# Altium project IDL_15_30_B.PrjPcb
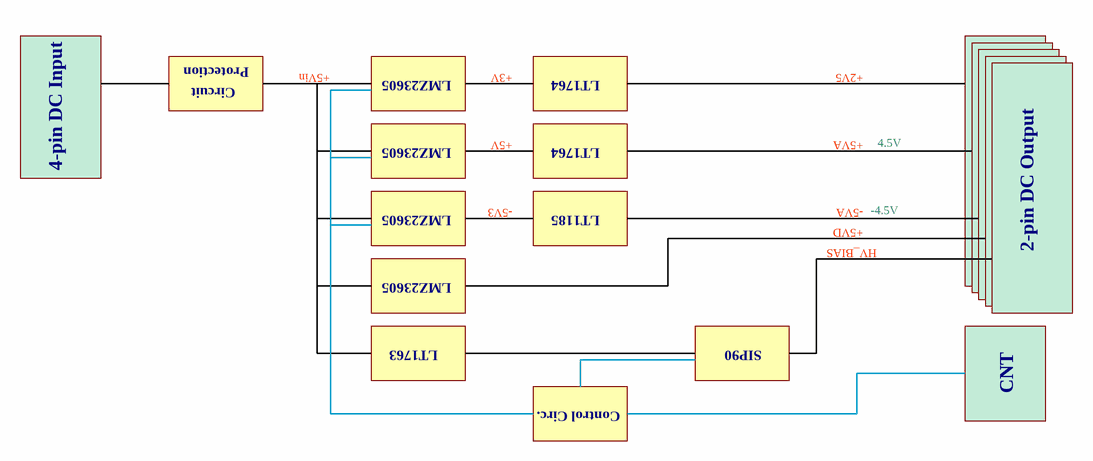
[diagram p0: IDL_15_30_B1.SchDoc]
Approved_By: Gary S. Varner; BoardName: CSciFi Power Supply; Designer: Peter Orel; Drawn_By: Peter Orel; IDLnum: IDL_15_30; ProjectName1: Compact SciFi Tracker; RevNum: B
3 sheets, 140 parts. Net scope: flat (ports and power ports of the same name join across sheets).
Board files: IDL_15_30_B.PcbDoc, IDL_15_30_B_pnl.PcbDoc
Sheets:
  IDL_15_30_B1.SchDoc
  IDL_15_30_B2.SchDoc
  PRJHdr_IDL_15_30_B.SchDoc

## Sheet IDL_15_30_B1.SchDoc: Functional Block Schematic
size 401 x 291 mm; DocumentNumber: 2; SheetNumber: 2; SheetTotal: 3

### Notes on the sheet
- Circuit
- Protection
- +5Vin
- LMZ23605
- +3V
- LT1764
- +2V5
- +5V
- +5VA
- 4.5V
- 4-pin DC Input
- -5V3
- LT1185
- -5VA
- +5VD
- -4.5V
- HV_BIAS
- 2-pin DC Output
- LT1763
- SIP90
- Control Circ.
- CNT

## Sheet IDL_15_30_B2.SchDoc: Power Supply Generation and Distribution
size 401 x 291 mm; DocumentNumber: 3; SheetNumber: 3; SheetTotal: 3
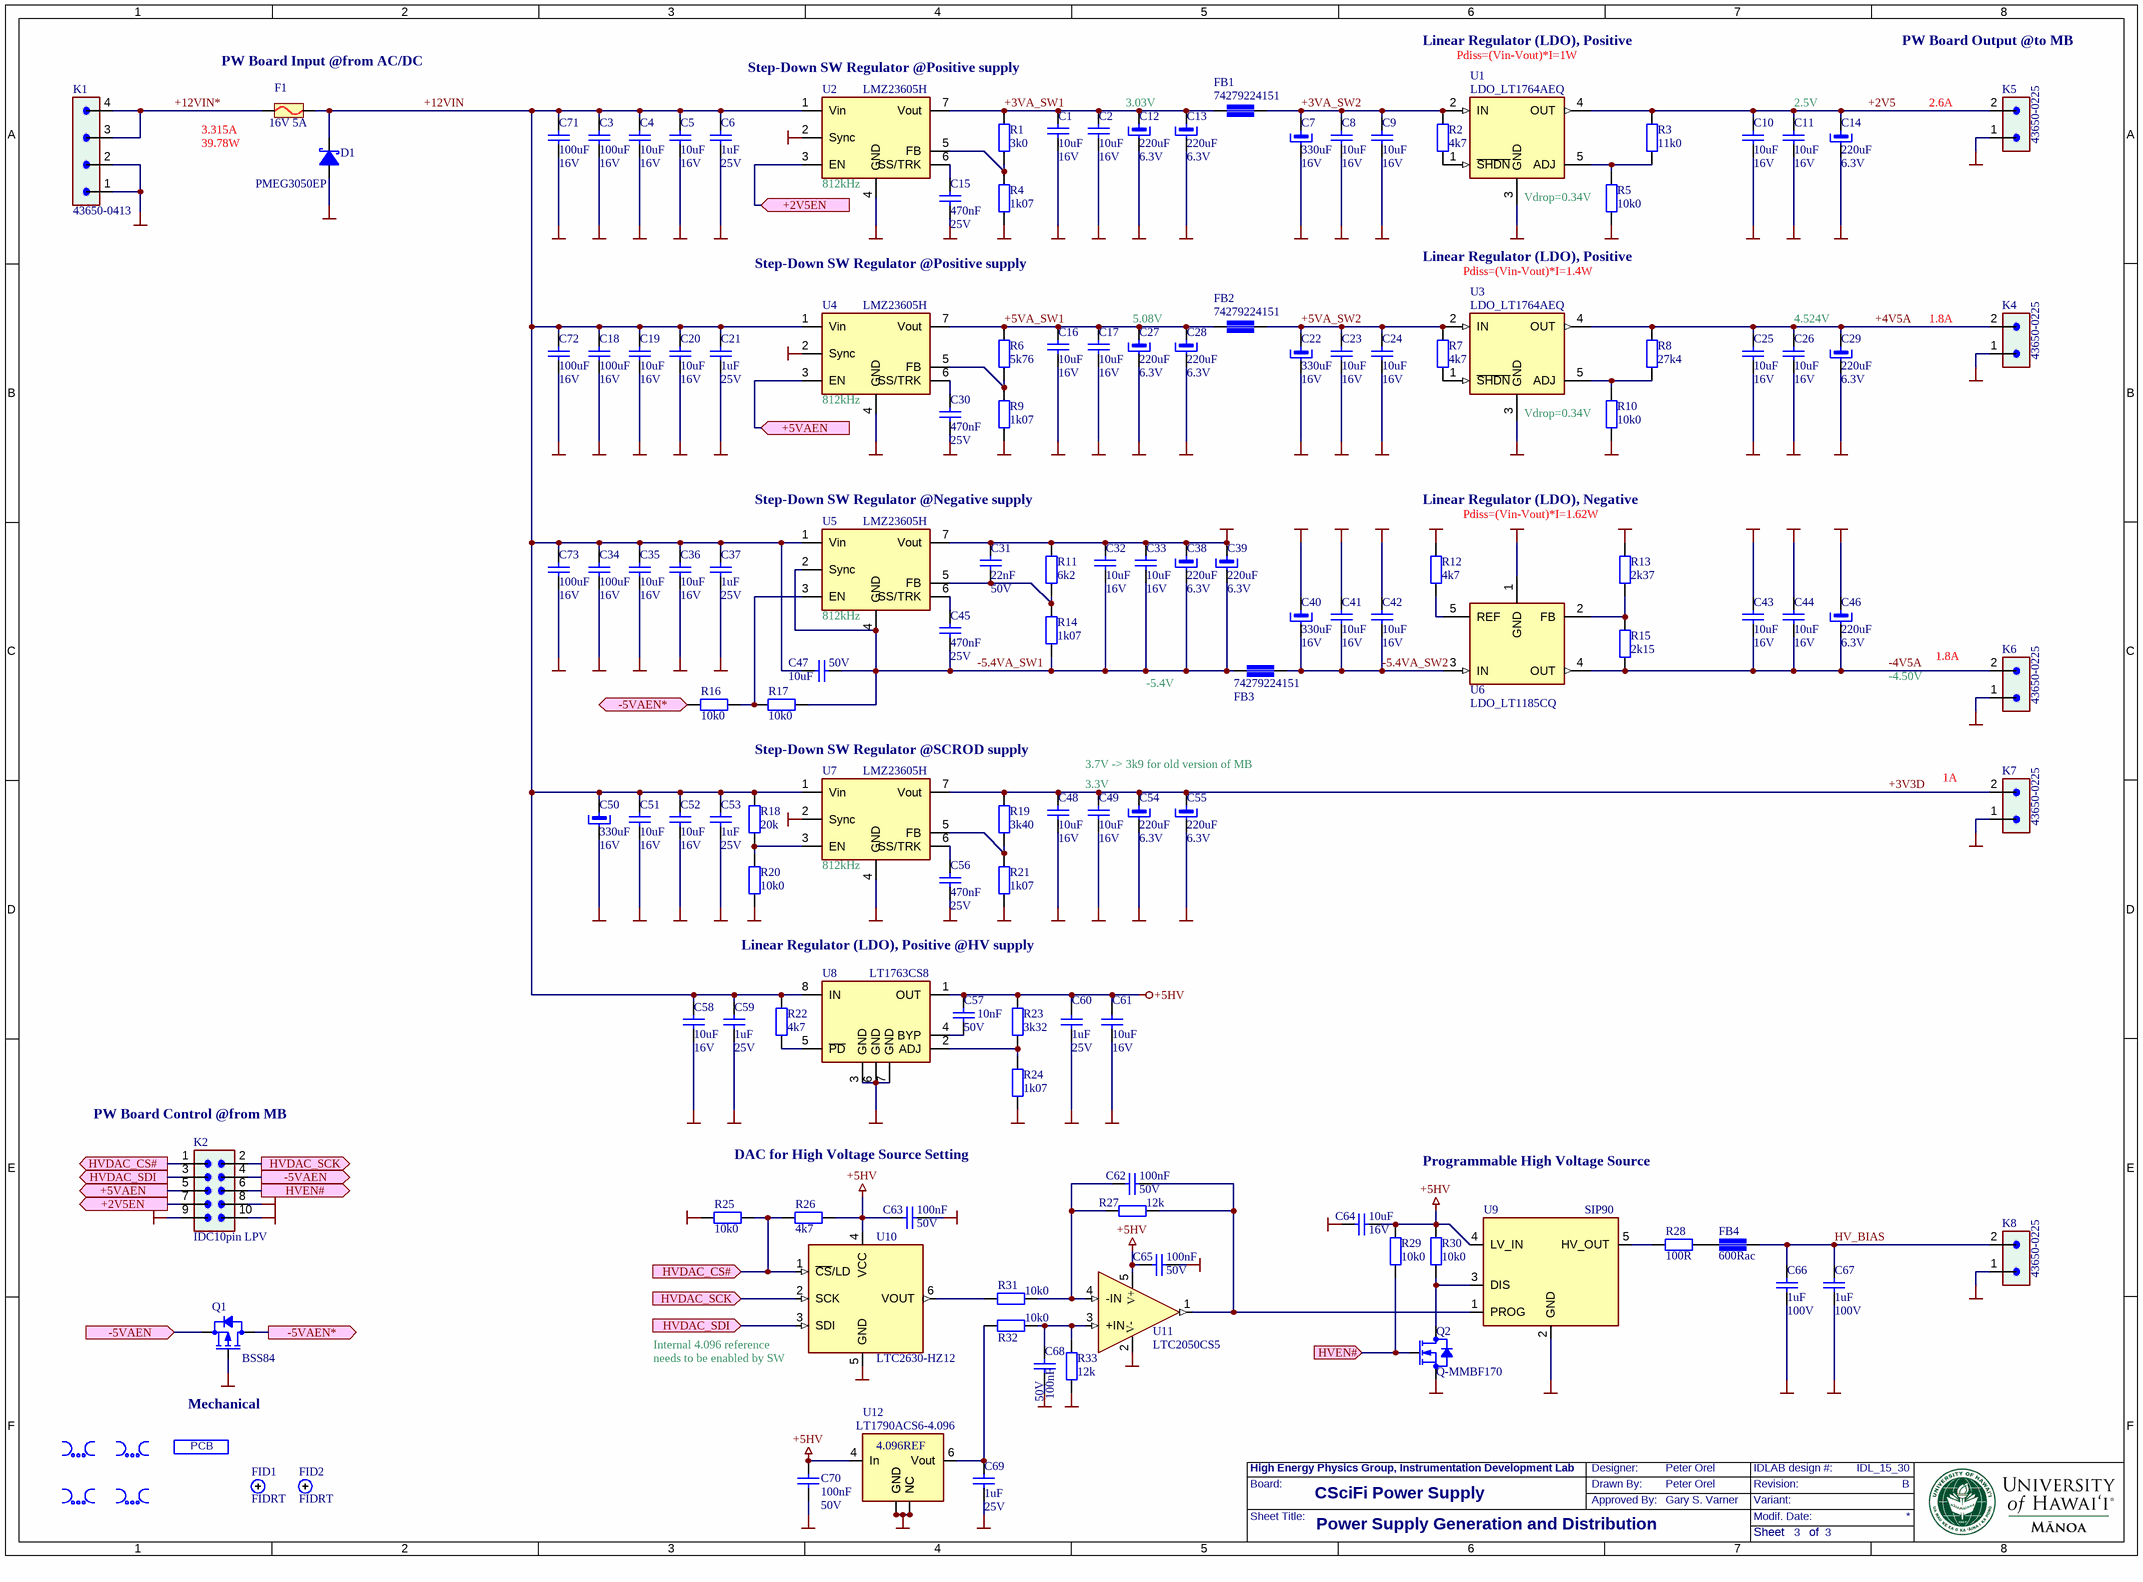
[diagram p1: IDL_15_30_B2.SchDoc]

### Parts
C1  10uF  Voltage rating: 16V  [CC1206N1R]
C2  10uF  Voltage rating: 16V  [CC1206N1R]
C3  100uF  Voltage rating: 16V  [CC1210N1R]
C4  10uF  Voltage rating: 16V  [CC1206N1R]
C5  10uF  Voltage rating: 16V  [CC1206N1R]
C6  1uF  Voltage rating: 25V  [CC0805N1R]
C7  330uF  Voltage rating: 16V  [CTC-D7343-43]
C8  10uF  Voltage rating: 16V  [CC1206N1R]
C9  10uF  Voltage rating: 16V  [CC1206N1R]
C10  10uF  Voltage rating: 16V  [CC1206N1R]
C11  10uF  Voltage rating: 16V  [CC1206N1R]
C12  220uF  Voltage rating: 6.3V  [CTC-D7343-43]
C13  220uF  Voltage rating: 6.3V  [CTC-D7343-43]
C14  220uF  Voltage rating: 6.3V  [CTC-D7343-43]
C15  470nF  Voltage rating: 25V  [CC0603RF1R]
C16  10uF  Voltage rating: 16V  [CC1206N1R]
C17  10uF  Voltage rating: 16V  [CC1206N1R]
C18  100uF  Voltage rating: 16V  [CC1210N1R]
C19  10uF  Voltage rating: 16V  [CC1206N1R]
C20  10uF  Voltage rating: 16V  [CC1206N1R]
C21  1uF  Voltage rating: 25V  [CC0805N1R]
C22  330uF  Voltage rating: 16V  [CTC-D7343-43]
C23  10uF  Voltage rating: 16V  [CC1206N1R]
C24  10uF  Voltage rating: 16V  [CC1206N1R]
C25  10uF  Voltage rating: 16V  [CC1206N1R]
C26  10uF  Voltage rating: 16V  [CC1206N1R]
C27  220uF  Voltage rating: 6.3V  [CTC-D7343-43]
C28  220uF  Voltage rating: 6.3V  [CTC-D7343-43]
C29  220uF  Voltage rating: 6.3V  [CTC-D7343-43]
C30  470nF  Voltage rating: 25V  [CC0603RF1R]
C31  22nF  Voltage rating: 50V  [CC0603RF1R]
C32  10uF  Voltage rating: 16V  [CC1206N1R]
C33  10uF  Voltage rating: 16V  [CC1206N1R]
C34  100uF  Voltage rating: 16V  [CC1210N1R]
C35  10uF  Voltage rating: 16V  [CC1206N1R]
C36  10uF  Voltage rating: 16V  [CC1206N1R]
C37  1uF  Voltage rating: 25V  [CC0805N1R]
C38  220uF  Voltage rating: 6.3V  [CTC-D7343-43]
C39  220uF  Voltage rating: 6.3V  [CTC-D7343-43]
C40  330uF  Voltage rating: 16V  [CTC-D7343-43]
C41  10uF  Voltage rating: 16V  [CC1206N1R]
C42  10uF  Voltage rating: 16V  [CC1206N1R]
C43  10uF  Voltage rating: 16V  [CC1206N1R]
C44  10uF  Voltage rating: 16V  [CC1206N1R]
C45  470nF  Voltage rating: 25V  [CC0603RF1R]
C46  220uF  Voltage rating: 6.3V  [CTC-D7343-43]
C47  10uF  Voltage rating: 50V  [CC1210N1R]
C48  10uF  Voltage rating: 16V  [CC1206N1R]
C49  10uF  Voltage rating: 16V  [CC1206N1R]
C50  330uF  Voltage rating: 16V  [CTC-D7343-43]
C51  10uF  Voltage rating: 16V  [CC1206N1R]
C52  10uF  Voltage rating: 16V  [CC1206N1R]
C53  1uF  Voltage rating: 25V  [CC0805N1R]
C54  220uF  Voltage rating: 6.3V  [CTC-D7343-43]
C55  220uF  Voltage rating: 6.3V  [CTC-D7343-43]
C56  470nF  Voltage rating: 25V  [CC0603RF1R]
C57  10nF  Voltage rating: 50V  [CC0603RF1R]
C58  10uF  Voltage rating: 16V  [CC1206N1R]
C59  1uF  Voltage rating: 25V  [CC0805N1R]
C60  1uF  Voltage rating: 25V  [CC0805N1R]
C61  10uF  Voltage rating: 16V  [CC1206N1R]
C62  100nF  Voltage rating: 50V  [CC0402N1R]
C63  100nF  Voltage rating: 50V  [CC0402N1R]
C64  10uF  Voltage rating: 16V  [CC1206N1R]
C65  100nF  Voltage rating: 50V  [CC0402N1R]
C66  1uF  Voltage rating: 100V  [CC1206N1R]
C67  1uF  Voltage rating: 100V  [CC1206N1R]
C68  100nF  Voltage rating: 50V  [CC0402N1R]
C69  1uF  Voltage rating: 25V  [CC0805N1R]
C70  100nF  Voltage rating: 50V  [CC0402N1R]
C71  100uF  Voltage rating: 16V  [CC1210N1R]
C72  100uF  Voltage rating: 16V  [CC1210N1R]
C73  100uF  Voltage rating: 16V  [CC1210N1R]
D1  PMEG3050EP  [SOD128]
F1  16V 5A  [FUSE4532-1]
FB1  74279224151  [FB2220N1R]
FB2  74279224151  [FB2220N1R]
FB3  74279224151  [FB2220N1R]
FB4  600Rac  [FB0603N1R]
FID1  FIDRT  [FIDRT50]  (net tie)
FID2  FIDRT  [FIDRT50]  (net tie)
K1  43650-0413  [CN43650-0413]
K2  IDC10pin LPV  [CN_20021521-00010T1LF]
K4  43650-0225  [CN43650-0225]
K5  43650-0225  [CN43650-0225]
K6  43650-0225  [CN43650-0225]
K7  43650-0225  [CN43650-0225]
K8  43650-0225  [CN43650-0225]
ME1  MILL_EAR  [MILLEAR2.0D]  (value not drawn)  (no BOM)
ME2  MILL_EAR  [MILLEAR2.0D]  (value not drawn)  (no BOM)
ME3  MILL_EAR  [MILLEAR2.0D]  (value not drawn)  (no BOM)
ME4  MILL_EAR  [MILLEAR2.0D]  (value not drawn)  (no BOM)
PCB1  PCB...  [LAYNUM4]  (value not drawn)
Q1  BSS84  [SOT23-1]
Q2  Q-MMBF170  [SOT23-1]
R1  3k0  [RC0603N1R]
R2  4k7  [RC0603N1R]
R3  11k0  [RC0603N1R]
R4  1k07  [RC0603N1R]
R5  10k0  [RC0603N1R]
R6  5k76  [RC0603N1R]
R7  4k7  [RC0603N1R]
R8  27k4  [RC0603N1R]
R9  1k07  [RC0603N1R]
R10  10k0  [RC0603N1R]
R11  6k2  [RC0603N1R]
R12  4k7  [RC0603N1R]
R13  2k37  [RC0603N1R]
R14  1k07  [RC0603N1R]
R15  2k15  [RC0603N1R]
R16  10k0  [RC0603N1R]
R17  10k0  [RC0603N1R]
R18  20k  [RC0603N1R]
R19  3k40  [RC0603N1R]
R20  10k0  [RC0603N1R]
R21  1k07  [RC0603N1R]
R22  4k7  [RC0603N1R]
R23  3k32  [RC0603N1R]
R24  1k07  [RC0603N1R]
R25  10k0  [RC0603N1R]
R26  4k7  [RC0603N1R]
R27  12k  [RC0603N1R]
R28  100R  [RC0603N1R]
R29  10k0  [RC0603N1R]
R30  10k0  [RC0603N1R]
R31  10k0  [RC0603N1R]
R32  10k0  [RC0603N1R]
R33  12k  [RC0603N1R]
U1  LDO_LT1764AEQ  [DDPAK]
U2  LMZ23605H  [DPAK127P1377X457-7N]
U3  LDO_LT1764AEQ  [DDPAK]
U4  LMZ23605H  [DPAK127P1377X457-7N]
U5  LMZ23605H  [DPAK127P1377X457-7N]
U6  LDO_LT1185CQ  [DDPAK]
U7  LMZ23605H  [DPAK127P1377X457-7N]
U8  LT1763CS8  [SOIC8-1]
U9  SIP90  [SIP90]
U10  LTC2630-HZ12  [SC70-6]
U11  LTC2050CS5  [SOT23-5]
U12  LT1790ACS6-4.096  [SOT23-6]

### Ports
+2V5EN (in), +2V5EN (out), +5VAEN (in), +5VAEN (out), -5VAEN (in), -5VAEN (out), -5VAEN* (in), -5VAEN* (out), HVDAC_CS# (in), HVDAC_CS# (out), HVDAC_SCK (in), HVDAC_SCK (out), HVDAC_SDI (in), HVDAC_SDI (out), HVEN# (in), HVEN# (out)

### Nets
+5HV: C57.2 C60.2 C61.2 C63.1 C64.1 C65.1 C70.2 R23.2 R26.1 R29.2 R30.2 U8.1(OUT) U9.4(LV_IN) U10.4(VCC) U11.5(V+) U12.4(In)
GND: C1.1 C2.1 C3.2 C4.1 C5.1 C6.1 C7.2 C8.1 C9.1 C10.1 C11.1 C12.2 C13.2 C14.2 C15.1 C16.1 C17.1 C18.2 C19.1 C20.1 C21.1 C22.2 C23.1 C24.1 C25.1 C26.1 C27.2 C28.2 C29.2 C30.1 C31.2 C32.2 C33.2 C34.2 C35.1 C36.1 C37.1 C38.1 C39.1 C40.1 C41.2 C42.2 C43.2 C44.2 C46.1 C48.1 C49.1 C50.2 C51.1 C52.1 C53.1 C54.2 C55.2 C56.1 C58.1 C59.1 C60.1 C61.1 C63.2 C64.2 C65.2 C66.1 C67.1 C68.1 C69.1 C70.1 C71.2 C72.2 C73.2 D1.2(A) K1.1 K1.2 K2.8 K2.9 K2.10 K4.1 K5.1 K6.1 K7.1 K8.1 Q1.1(G) Q2.2(S) R4.1 R5.1 R9.1 R10.1 R11.2 R12.2 R13.2 R20.2 R21.1 R24.1 R25.2 R33.1 U1.3(GND) U2.2(Sync) U2.4(GND) U3.3(GND) U4.2(Sync) U4.4(GND) U5.7(Vout) U6.1(GND) U7.2(Sync) U7.4(GND) U8.3(GND) U8.6(GND) U8.7(GND) U9.2(GND) U10.5(GND) U11.2(V-) U12.1(GND) U12.2(GND) U12.3(NC) U12.5(NC)
+2V5: C10.2 C11.2 C14.1 K5.2 R3.2 U1.4(OUT)  [project net +2V5_3]
+2V5EN: K2.7 U2.3(EN) ; port +2V5EN
+3V3D: C48.2 C49.2 C54.1 C55.1 K7.2 R19.2 U7.7(Vout)  [project net +3V3D_3]
+3VA_SW1: C1.2 C2.2 C12.1 C13.1 FB1.1 R1.2 U2.7(Vout)  [project net +3VA_SW1_3]
+3VA_SW2: C7.1 C8.2 C9.2 FB1.2 R2.2 U1.2(IN)  [project net +3VA_SW2_3]
+4V5A: C25.2 C26.2 C29.1 K4.2 R8.2 U3.4(OUT)  [project net +4V5A_3]
+5VA_SW1: C16.2 C17.2 C27.1 C28.1 FB2.1 R6.2 U4.7(Vout)  [project net +5VA_SW1_3]
+5VA_SW2: C22.1 C23.2 C24.2 FB2.2 R7.2 U3.2(IN)  [project net +5VA_SW2_3]
+5VAEN: K2.5 U4.3(EN) ; port +5VAEN
+12VIN: C3.1 C4.2 C5.2 C6.2 C18.1 C19.2 C20.2 C21.2 C34.1 C35.2 C36.2 C37.2 C47.1 C50.1 C51.2 C52.2 C53.2 C58.2 C59.2 C71.1 C72.1 C73.1 D1.1(C) F1.2 R18.2 R22.2 U2.1(Vin) U4.1(Vin) U5.1(Vin) U7.1(Vin) U8.8(IN)  [project net +12VIN_3]
+12VIN*: F1.1 K1.3 K1.4  [project net +12VIN*_3]
-4V5A: C43.1 C44.1 C46.2 K6.2 R15.1 U6.4(OUT)  [project net -4V5A_3]
-5.4VA_SW1: C32.1 C33.1 C38.2 C39.2 C45.1 C47.2 FB3.1 R14.1 R17.2 U5.2(Sync) U5.4(GND)  [project net -5.4VA_SW1_3]
-5.4VA_SW2: C40.2 C41.1 C42.1 FB3.2 U6.3(IN)  [project net -5.4VA_SW2_3]
-5VAEN: K2.4 Q1.2(S) ; port -5VAEN
-5VAEN*: Q1.3(D) R16.1 ; port -5VAEN*
HV_BIAS: C66.2 C67.2 FB4.2 K8.2  [project net HV_BIAS_3]
HVDAC_CS#: K2.1 R25.1 R26.2 U10.1(~{CS}/LD) ; port HVDAC_CS#
HVDAC_SCK: K2.2 U10.2(SCK) ; port HVDAC_SCK
HVDAC_SDI: K2.3 U10.3(SDI) ; port HVDAC_SDI
HVEN#: K2.6 Q2.1(G) R29.1 ; port HVEN#
NetC15_2: C15.2 U2.6(SS/TRK)
NetC30_2: C30.2 U4.6(SS/TRK)
NetC31_1: C31.1 R11.1 R14.2 U5.5(FB)
NetC45_2: C45.2 U5.6(SS/TRK)
NetC56_2: C56.2 U7.6(SS/TRK)
NetC57_1: C57.1 U8.4(BYP)
NetC62_1: C62.1 R27.1 R31.1 U11.4(-IN)
NetC62_2: C62.2 R27.2 U9.1(PROG) U11.1(OUT)
NetC68_2: C68.2 R32.1 R33.2 U11.3(+IN)
NetC69_2: C69.2 R32.2 U12.6(Vout)
NetFB4_1: FB4.1 R28.2
NetQ2_3: Q2.3(D) R30.1 U9.3(DIS)
NetR1_1: R1.1 R4.2 U2.5(FB)
NetR2_1: R2.1 U1.1(~{SHDN})
NetR3_1: R3.1 R5.2 U1.5(ADJ)
NetR6_1: R6.1 R9.2 U4.5(FB)
NetR7_1: R7.1 U3.1(~{SHDN})
NetR8_1: R8.1 R10.2 U3.5(ADJ)
NetR12_1: R12.1 U6.5(REF)
NetR13_1: R13.1 R15.2 U6.2(FB)
NetR16_2: R16.2 R17.1 U5.3(EN)
NetR18_1: R18.1 R20.1 U7.3(EN)
NetR19_1: R19.1 R21.2 U7.5(FB)
NetR22_1: R22.1 U8.5(~{PD})
NetR23_1: R23.1 R24.2 U8.2(ADJ)
NetR28_1: R28.1 U9.5(HV_OUT)
NetR31_2: R31.2 U10.6(VOUT)

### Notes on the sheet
- (near F1) PW Board Input @from AC/DC
- Step-Down SW Regulator @Positive supply
- Linear Regulator (LDO), Positive
- Pdiss=(Vin-Vout)*I=1W
- PW Board Output @to MB
- (near F1) 3.315A
- (near F1) 39.78W
- (near C12) 3.03V
- 2.5V
- (near K5) 2.6A
- (near U2) 812kHz
- Vdrop=0.34V
- Pdiss=(Vin-Vout)*I=1.4W
- (near C27) 5.08V
- 4.524V
- (near K4) 1.8A
- (near U4) 812kHz
- Step-Down SW Regulator @Negative supply
- Linear Regulator (LDO), Negative
- Pdiss=(Vin-Vout)*I=1.62W
- (near U5) 812kHz
- -5.4V
- -4.50V
- (near K6) 1.8A
- Step-Down SW Regulator @SCROD supply
- 3.7V -> 3k9 for old version of MB
- (near C49) 3.3V
- (near K7) 1A
- (near U7) 812kHz
- Linear Regulator (LDO), Positive @HV supply
- (near K2) PW Board Control @from MB
- DAC for High Voltage Source Setting
- Programmable High Voltage Source
- (near U10) Internal 4.096 reference
- (near U10) needs to be enabled by SW
- Mechanical

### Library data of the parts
C1 C2 C4 C5 C8-C11 C16 C17 C19 C20 C23-C26 C32 C33 C35 C36 C41-C44 C48 C49 C51 C52 C58 C61 C64 = CAPCC1206_10U_16VX7R: Capacitor chip ceramic 1206 16V X7R; Manufacturer: TDK; Manufacturer No: C3216X7R1C106M160AC; Tech: SMDR
C3 C18 C34 C71-C73 = CAPCC1210_100U_16VX5R: Capacitor chip ceramic 1210 16V X5R; Manufacturer: Kemet; Manufacturer No: C1210C107M4PAC7800; Tech: SMDR
C6 C21 C37 C53 C59 C60 C69 = CAPCC0805_1U_25VX7R: Capacitor chip ceramic 0805 25V X7R; Manufacturer: Kemet; Manufacturer No: C0805C105K3RACTU; Tech: SMDR
C7 C22 C40 C50 = CAPT7343_330U_16V: Capacitor tantal smd 7343-43 16V 50mResr; Manufacturer: Kemet; Manufacturer No: T521X337M016ATE050; Tech: SMDR
C12-C14 C27-C29 C38 C39 C46 C54 C55 = CAPT7343_220U_6.3V: Capacitor Aluminium Polymer, High Ripple, smd 7343-43 6.3V 7mResr; Manufacturer: Panasonic; Manufacturer No: EEF-UE0J221LR; Tech: SMDR
C15 C30 C45 C56 = CAPCC0603_1_470N_50VX7R: Capacitor chip ceramic 0603 25V X7R; Manufacturer: Murata; Manufacturer No: GRM188R71E474KA12D; Tech: SMDR
C31 = CAPCC0603_1_22N_50VX7R: Capacitor chip ceramic 0603 50V X7R; Manufacturer: TDK; Manufacturer No: C1608X7R1H223K080AA; Tech: SMDR
C47 = CAPCC1210_10U_50VX7R: Capacitor chip ceramic 1210 50V X7R; Manufacturer: TDK; Manufacturer No: GRM32ER71H106KA12L; Tech: SMDR
C57 = CAPCC0603_1_10N_50VX7R: Capacitor chip ceramic 0603 50V X7R; Manufacturer: Murata; Manufacturer No: GRM188R71H103KA01D; Tech: SMDR
C62 C63 C65 C68 C70 = CAPCC0402_100000P_50VX7R: Capacitor chip ceramic 0402 50V X7R; Manufacturer: TDK; Manufacturer No: C1005X7R1H104K050BB; Tech: SMDR
C66 C67 = CAPCC1206_1U_100VX7R: Capacitor chip ceramic 1206 100V X7R; Manufacturer: TDK; Manufacturer No: C3216X7R2A105K160AA; Tech: SMDR
D1 = D-PMEG3050EP: Schottky diode 6A 30V 500ns 0.36Vf; Manufacturer: NXP; Manufacturer No: PMEG3050EP,115; Tech: SMDR
F1 = FUSE-MINISMDC260F/16-2: PolySwitch Fuse SMD 1812 16V 5A; Manufacturer: TE Connectivity; Tech: SMDR
FB1-FB3 = FB2220-74279224151: Feritte filter smd 2220 5A 10mRdc 150Rac; Manufacturer: Wurth; Tech: SMDR
FB4 = FB0603-600R_0.2A: Feritte filter smd 0603 0.2A 1Rdc; Manufacturer: Murata; Manufacturer No: BLM18HG601SN1; Tech: SMDR
FID1 FID2 = FIDRT: Fiducial top round open mask; Sort: 800; Tech: MECH
K1 = CN-43650-0413: Connector Header 4 pin rigth-angle SMD 3mm 4A; Manufacturer No: 436500413; Manufacturer: Molex; Tech: THDW
K2 = CN_IDC10V_SMD1.27: Connector IDC 10 pin vertical 1.27mm SMD; Manufacturer No: 20021521-00010T1LF; Manufacturer: FCI
K4-K8 = CN-43650-0225: Connector Header 2 pin vertical SMD 3mm 4A; Manufacturer No: 0436500225; Manufacturer: Molex; Tech: THDW
ME1-ME4 = MILL_EAR: Milling ear 2.0mm; Comment2: 2 x R2.0mm; Sort: 800; Tech: MECH
PCB1 = PCB-FR41.6MM4LAY: Printed Circuit Board 4 layer FR4 1.6mm 35um Cu; Manufacturer: PCB Universe; Manufacturer No: IDL_15_XX; Tech: MECH
Q1 = Q-BSS84: P-Channel MOSFET 50V 0.13A 10R; Manufacturer: NXP; Tech: SMDR
Q2 = Q-MMBF170: N-Channel MOSFET 60V, 0.5A, 0.3W; Manufacturer: ON Semiconductor; Tech: SMDR
R1 = RES0603-1-3k00-1%100PPM: Chip Resistor 0603 100mW 1% 100ppm; Manufacturer: Panasonic; Manufacturer No: ERJ-3EKF3001V; Tech: SMDR
R2 R7 R12 R22 R26 = RES0603-1-4k7-1%100PPM: Chip Resistor 0603 100mW 1% 100ppm; Manufacturer: Panasonic; Manufacturer No: ERJ-3EKF4701V; Tech: SMDR
R3 = RES0603-1-11k0-1%100PPM: Chip Resistor 0603 100mW 1% 100ppm; Manufacturer: Panasonic; Manufacturer No: ERJ-3EKF1102V; Tech: SMDR
R4 R9 R14 R21 R24 = RES0603-1-1k07-1%100PPM: Chip Resistor 0603 100mW 1% 100ppm; Manufacturer: Panasonic; Manufacturer No: ERJ-3EKF1071V; Tech: SMDR
R5 R10 R16 R17 R20 R25 R29-R32 = RES0603-1-10k0-1%100PPM: Chip Resistor 0603 100mW 1% 100ppm; Manufacturer: Panasonic; Manufacturer No: ERJ-3EKF1002V; Tech: SMDR
R6 = RES0603-1-5k76-1%100PPM: Chip Resistor 0603 100mW 1% 100ppm; Manufacturer: Panasonic; Manufacturer No: ERJ-3EKF5761V; Tech: SMDR
R8 = RES0603-1-27k4-1%100PPM: Chip Resistor 0603 100mW 1% 100ppm; Manufacturer: Panasonic; Manufacturer No: ERJ-3EKF2742V; Tech: SMDR
R11 = RES0603-1-6k20-1%100PPM: Chip Resistor 0603 100mW 1% 100ppm; Manufacturer: Panasonic; Manufacturer No: ERJ-3EKF6201V; Tech: SMDR
R13 = RES0603-2370-1%100PPM: Chip Resistor 0603 100mW 1% 100ppm; Manufacturer: Panasonic; Manufacturer No: ERJ-3EKF2371V; Tech: SMDR
R15 = RES0603-1-2k15-1%100PPM_1: Chip Resistor 0603 100mW 1% 100ppm; Manufacturer: Panasonic; Manufacturer No: ERJ-3EKF2151V; Tech: SMDR
R18 = RES0603-1-20k0-1%100PPM: Chip Resistor 0603 100mW 1% 100ppm; Manufacturer: Panasonic; Manufacturer No: ERJ-3EKF2002V; Tech: SMDR
R19 = RES0603-1-3.40K-1%100PPM: Chip Resistor 0603 100mW 1% 100ppm; Manufacturer: Yageo; Manufacturer No: RC0603FR-073K4L; Tech: SMDR
R23 = RES0603-1-3k32-1%100PPM: Chip Resistor 0603 100mW 1% 100ppm; Manufacturer: Panasonic; Manufacturer No: ERJ-3EKF3321V; Tech: SMDR
R27 R33 = RES0603-1-12k0-1%100PPM: Chip Resistor 0603 100mW 1% 100ppm; Manufacturer: Panasonic; Manufacturer No: ERJ-3EKF1202V; Tech: SMDR
R28 = RES0603-0-100R-1%100PPM: Chip Resistor 0603 100mW 1% 100ppm; Manufacturer: Panasonic; Manufacturer No: ERJ-3EKF1000V; Tech: SMDR
U1 U3 = LDO_LT1764AEQ: Low drop low noise regulator 3A  DDPak; Manufacturer: Linear Technology; Manufacturer No: LT1764AEQ#TRPBF; Comment2: 3A, 1.21 to 20Vout,; Tech: SMDR
U2 U4 U5 U7 = DCDC_LMZ23605H: 3A SIMPLE SWITCHER® Power Module for High Output Voltage; Manufacturer: Texas Instruments; Manufacturer No: LMZ23605TZE/NOPB; Tech: SMDR
U6 = LDO_LT1185CQ: Negative Low drop regulator 3A; Manufacturer: Linear Technologies, Farnell; Manufacturer No: LT1185CQ#PBF; Comment2: adjVout 30Vin 3A 0.75Vdrop; Tech: SMDR
U8 = LDO_LT1763CS8#PBF: 500mA, Low Noise, LDO; Manufacturer: Linear Technology; Tech: SMDR
U9 = HVPS-HV-SIP90: Regulated, Low Ripple High Voltage DC/DC Converter; Manufacturer: Emco; Comment2: 3-6.7V Vin, 25-90 VDC, 1mA max; Tech: TMDW
U10 = DAC_LTC2630-HZ12: 12-Bit Vout DAC 12 bit 4.096IntREF ResetToZero; Manufacturer: Linear Technology; Manufacturer No: LTC2630AISC6-HZ12#TRMPBF; Comment2: 12bit 4.096Vout Mid-Scale; Tech: SMDR
U11 = OPAMP_LTC2050CS5: Zero-Drift Operational Amplifier; Manufacturer: Linear Technology; Manufacturer No: LTC2050CS5#TRMPBF; Tech: SMDR
U12 = REF_LT1790ACS6-4.096: Reference 4.096V 10ppm 5mA; Manufacturer: Linear Technology; Manufacturer No: LT1790ACS6-4.096#TRMPBF; Tech: SMDR

## Sheet PRJHdr_IDL_15_30_B.SchDoc: Title_doc_parameter!
size 401 x 291 mm; DocumentNumber: 1; SheetNumber: 1; SheetTotal: 3; Project_IT-Code: XXXX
